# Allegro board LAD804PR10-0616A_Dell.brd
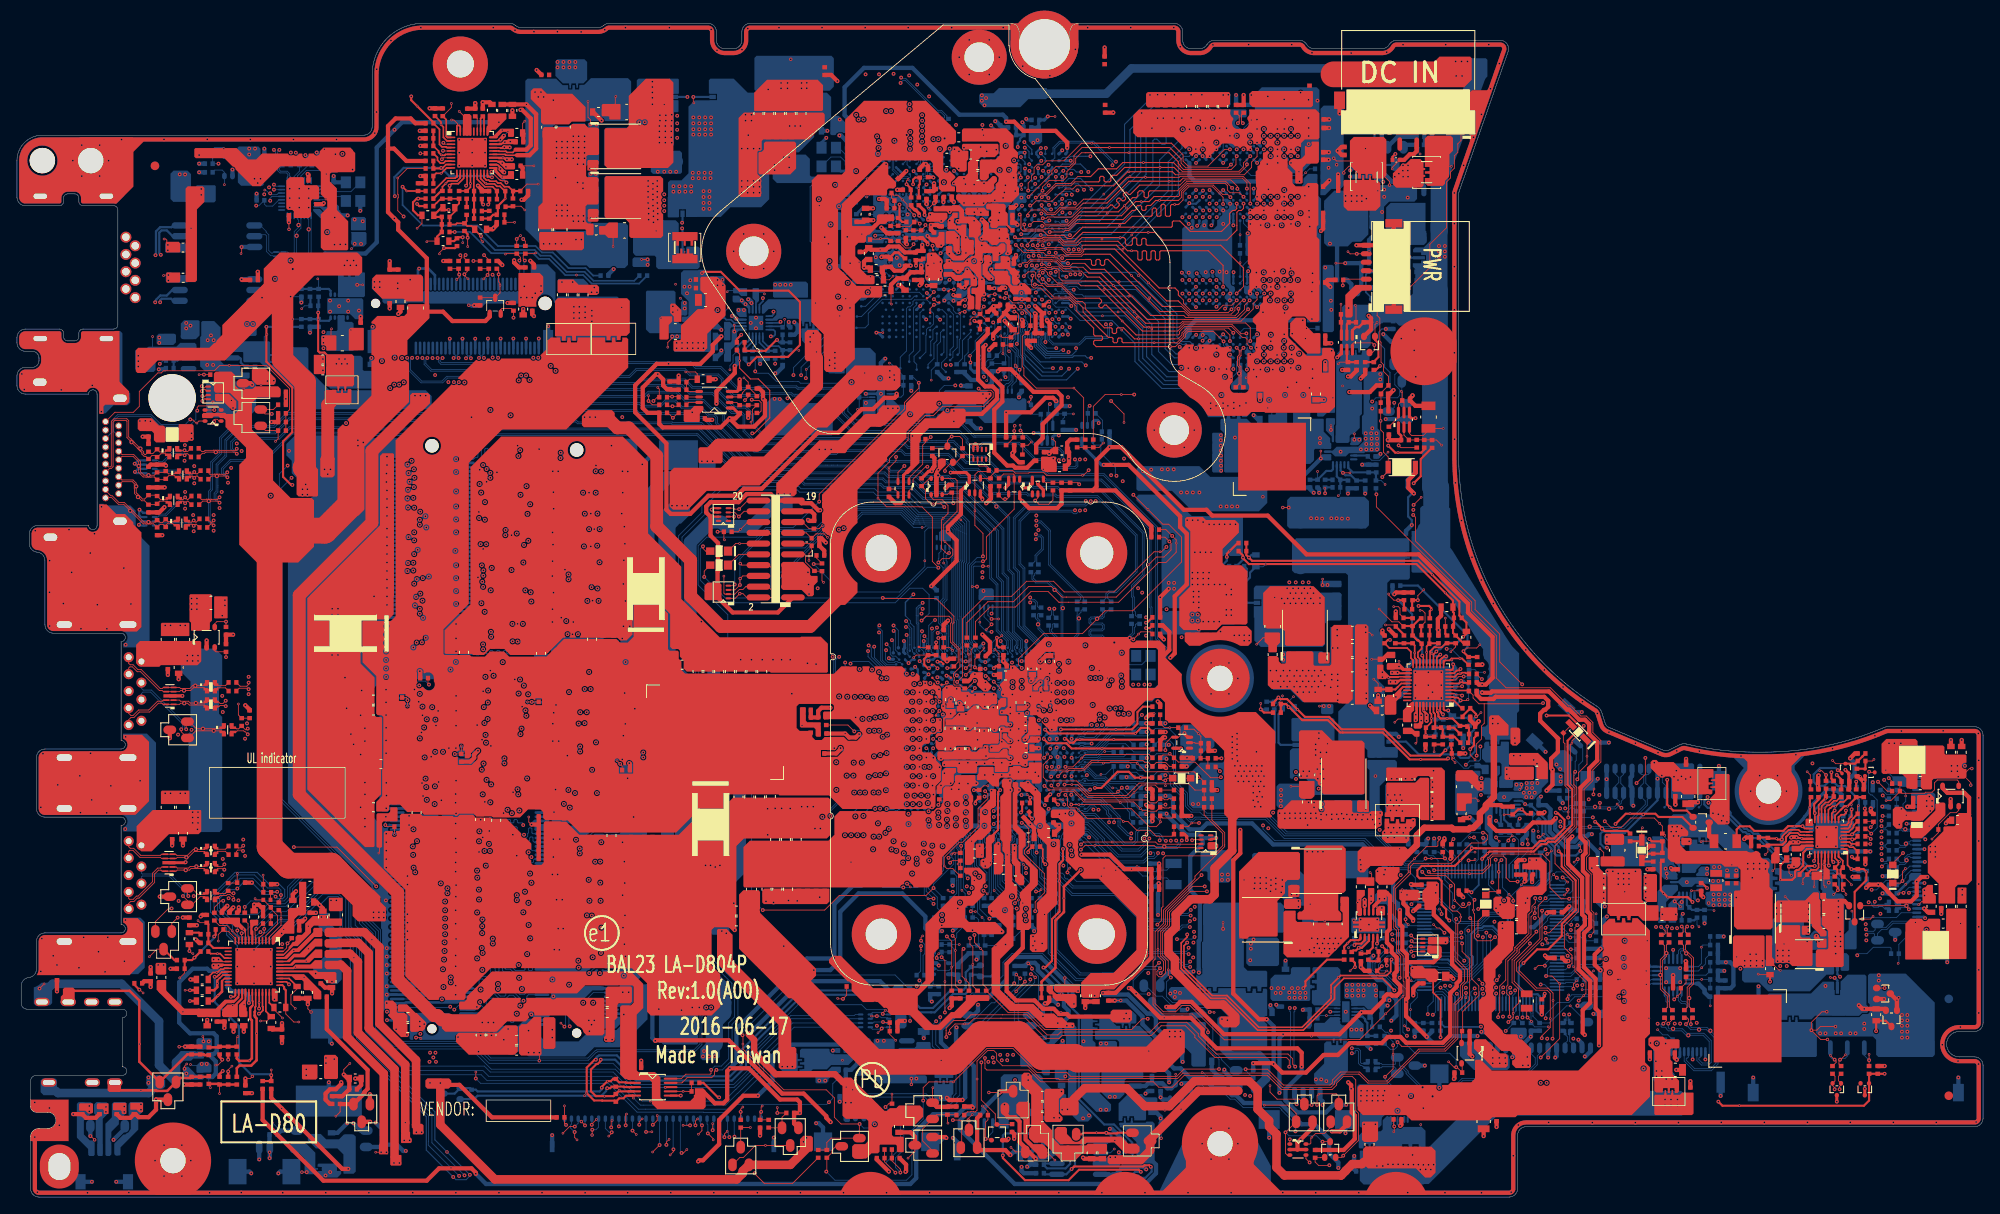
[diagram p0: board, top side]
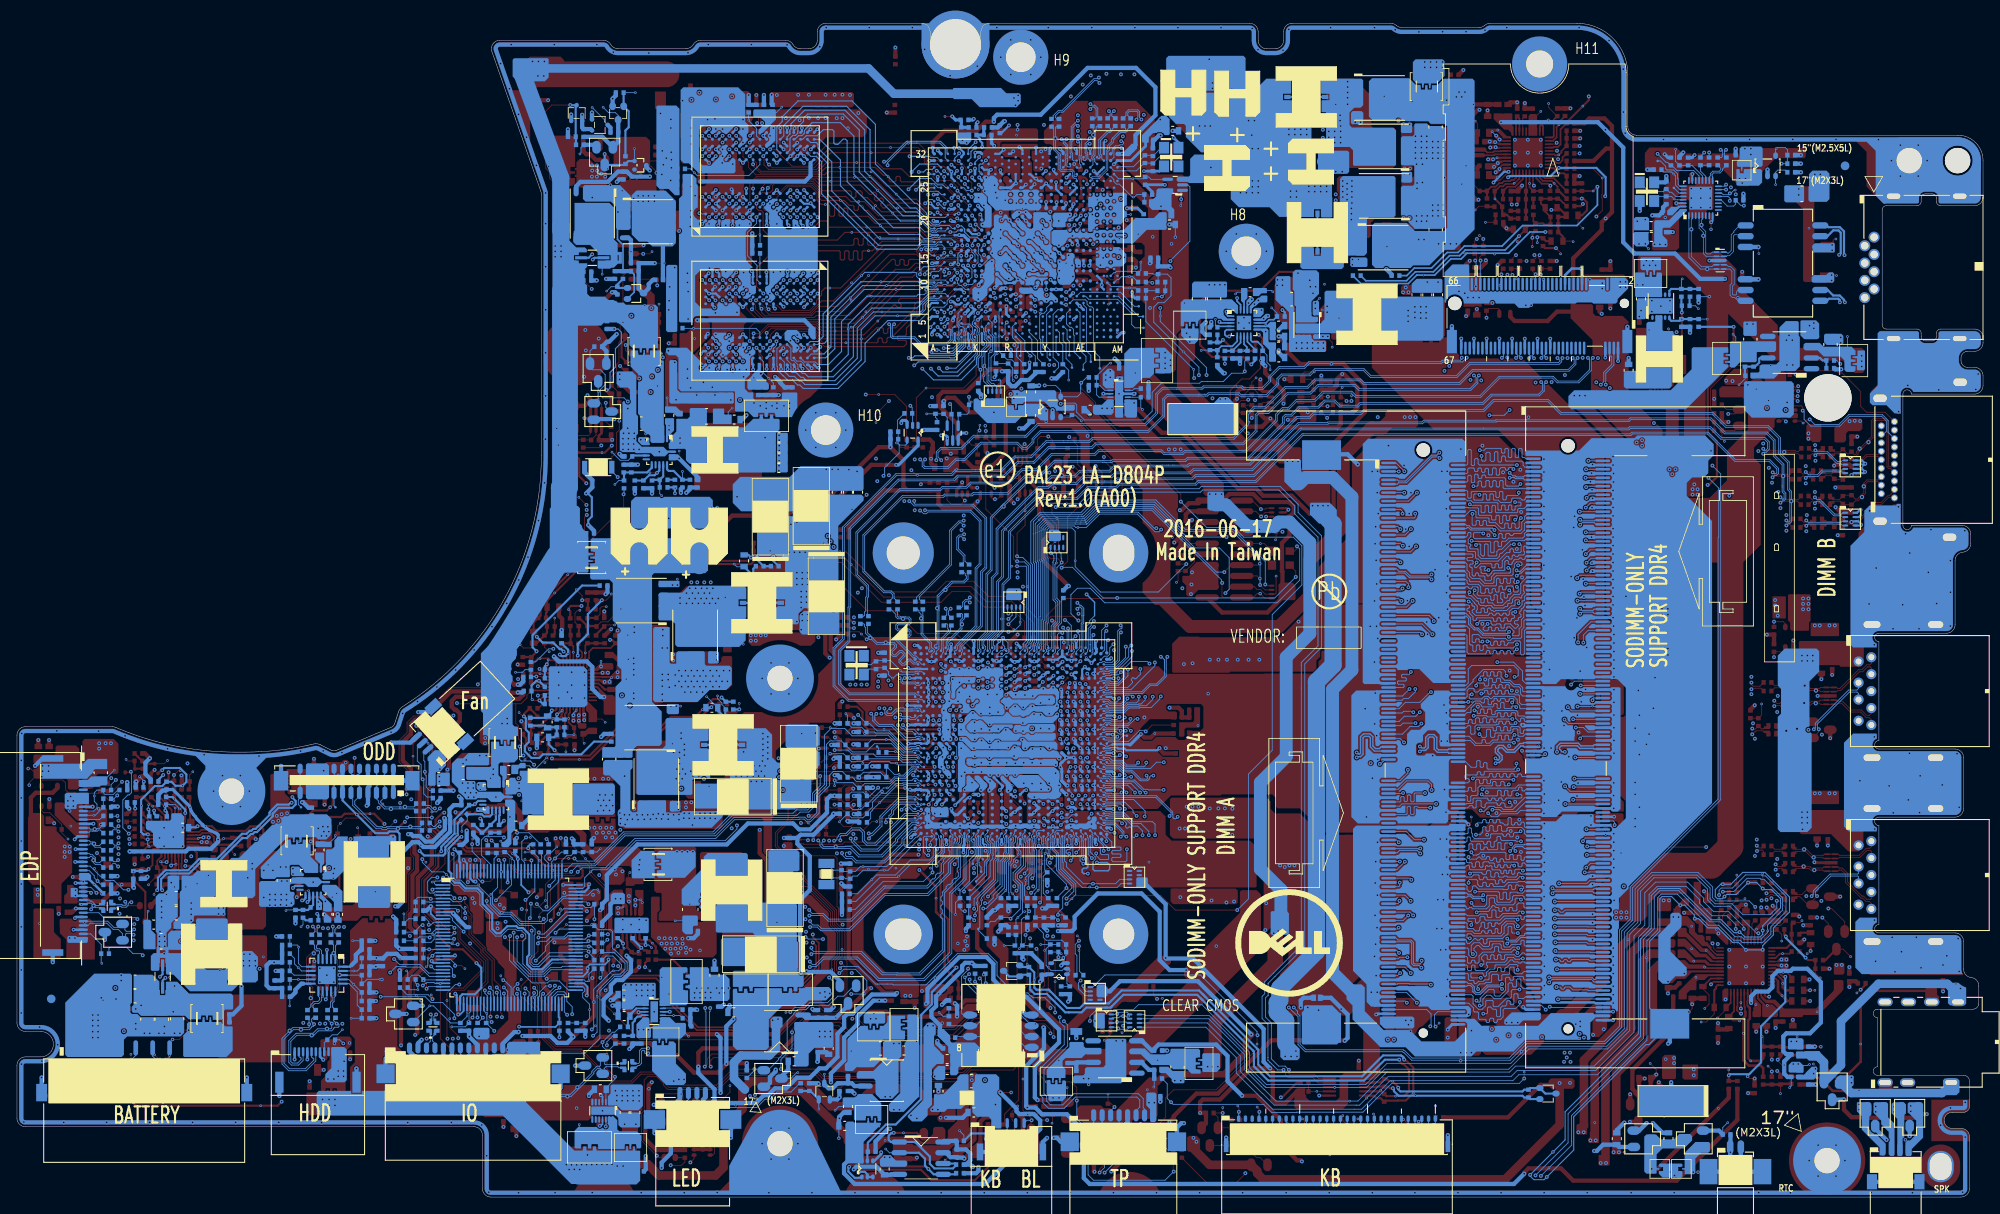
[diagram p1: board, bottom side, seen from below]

Outline 231.9 x 138.5 mm; copper layers: TOP, VCC, IN1, IN2, GND, BOTTOM. Coordinates in mm from the lower left corner of the outline.
Outline path: 0,122.3 arc(0.88,124.42) 3,125.3 40.9,125.3 arc(41.61,125.59) 41.9,126.3 41.9,132.5 arc(43.66,136.74) 47.9,138.5 58.13,138.5 arc(58.49,138.44) 58.8,138.25 arc(59.1,138.06) 59.46,138 68.54,138 arc(68.9,138.06) 69.2,138.25 arc(69.51,138.44) 69.87,138.5 81.5,138.5 arc(82.21,138.21) 82.5,137.5 82.5,136.5 arc(82.79,135.79) 83.5,135.5 84.5,135.5 arc(85.21,135.79) 85.5,136.5 85.5,137.5 arc(85.79,138.21) 86.5,138.5 117.2,138.5 arc(117.91,138.21) 118.2,137.5 118.2,136 arc(121.2,133) 124.2,136 124.2,137.5 arc(124.49,138.21) 125.2,138.5 136.5,138.5 arc(137.21,138.21) 137.5,137.5 137.5,136.5 arc(137.79,135.79) 138.5,135.5 139.5,135.5 arc(140,135.63) 140.37,136 arc(140.73,136.37) 141.23,136.5 151.27,136.5 arc(151.77,136.37) 152.13,136 arc(152.5,135.63) 153,135.5 161,135.5 arc(161.5,135.63) 161.87,136 arc(162.23,136.37) 162.73,136.5 174.94,136.5 arc(175.76,136.08) 175.88,135.17 170.11,118.66 arc(170.06,118.5) 170.05,118.33 170.05,87.5 arc(174.41,70.58) 186.41,57.88 arc(186.71,57.6) 186.91,57.23 187.34,55.9 arc(187.51,55.61) 187.79,55.41 194.19,52.72 arc(194.52,52.66) 194.85,52.74 196.1,53.36 arc(196.5,53.48) 196.92,53.46 arc(200.96,52.74) 205.05,52.5 206.05,52.5 arc(213.3,53.24) 220.25,55.42 arc(220.44,55.48) 220.64,55.5 230.9,55.5 arc(231.61,55.21) 231.9,54.5 231.9,20.54 arc(231.61,19.83) 230.9,19.54 229.1,19.54 arc(227.6,18.04) 229.1,16.54 230.9,16.54 arc(231.61,16.25) 231.9,15.54 231.9,9.3 arc(231.61,8.59) 230.9,8.3 178,8.3 arc(177.29,8.01) 177,7.3 177,1 arc(176.71,0.29) 176,0 2.6,0 arc(1.89,0.29) 1.6,1 1.6,7.1 arc(1.89,7.81) 2.6,8.1 3.65,8.1 arc(4.6,9.05) 3.65,10 2.3,10 arc(1.8,10.21) 1.6,10.7 1.6,13.67 arc(1.8,14.16) 2.3,14.37 12.45,14.37 arc(12.95,14.87) 12.45,15.37 12.45,21.17 arc(12.95,21.67) 12.45,22.17 1.2,22.17 arc(0.71,22.37) 0.5,22.87 0.5,24.91 arc(0.76,25.58) 1.4,25.91 arc(2.04,26.23) 2.3,26.9 2.3,30.17 arc(2.59,30.87) 3.3,31.17 12.28,31.17 arc(12.78,31.67) 12.28,32.17 12.28,43.83 arc(12.78,44.33) 12.28,44.83 3.3,44.83 arc(2.59,45.13) 2.3,45.83 2.3,51.87 arc(2.59,52.57) 3.3,52.87 12.28,52.87 arc(12.78,53.37) 12.28,53.87 12.28,65.53 arc(12.78,66.03) 12.28,66.53 4.3,66.53 arc(3.59,66.83) 3.3,67.53 3.3,75.1 arc(3.03,75.78) 2.38,76.1 arc(1.73,76.42) 1.46,77.09 1.46,78.25 arc(1.75,78.96) 2.46,79.25 8.45,79.25 arc(8.95,78.75) 9.45,79.25 9.45,94.75 arc(8.95,95.25) 8.45,94.75 1,94.75 arc(0.29,95.04) 0,95.75 0,96.9 arc(0.29,97.61) 1,97.9 1.8,97.9 arc(2.37,98.13) 2.6,98.7 2.6,99 arc(2.37,99.57) 1.8,99.8 1,99.8 arc(0.29,100.09) 0,100.8 0,101.42 arc(0.29,102.13) 1,102.42 5,102.42 arc(5.35,102.28) 5.5,101.92 5.5,101.52 arc(5.65,101.17) 6,101.02 6.8,101.02 arc(7.15,101.17) 7.3,101.52 7.3,101.92 arc(7.45,102.28) 7.8,102.42 11.4,102.42 arc(11.75,102.57) 11.9,102.92 11.9,116.48 arc(11.75,116.83) 11.4,116.98 7.8,116.98 arc(7.45,117.12) 7.3,117.48 7.3,117.88 arc(7.15,118.23) 6.8,118.38 6,118.38 arc(5.65,118.23) 5.5,117.88 5.5,117.48 arc(5.35,117.12) 5,116.98 1,116.98 arc(0.29,117.27) 0,117.98 0,122.3

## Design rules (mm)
net group CLK: nets 48M_X1 48M_X2
net group CLK_PCIE_LAN: nets CLK_PCIE_LAN CLK_PCIE_LAN#
net group CLK_PCIE_WLAN: nets CLK_PCIE_WLAN CLK_PCIE_WLAN#
net group CLK_PEG_VGA: nets CLK_PEG_VGA CLK_PEG_VGA#
net group DDRA_CLK0: nets DDRA_CLK0 DDRA_CLK0#
net group DDRA_CLK1: nets DDRA_CLK1 DDRA_CLK1#
net group DDRAB_SDQS0: nets DDRAB_SDQS0 DDRAB_SDQS0#
net group DDRAB_SDQS1: nets DDRAB_SDQS1 DDRAB_SDQS1#
net group DDRAB_SDQS2: nets DDRAB_SDQS2 DDRAB_SDQS2#
net group DDRAB_SDQS3: nets DDRAB_SDQS3 DDRAB_SDQS3#
net group DDRAB_SDQS4: nets DDRAB_SDQS4 DDRAB_SDQS4#
net group DDRAB_SDQS5: nets DDRAB_SDQS5 DDRAB_SDQS5#
net group DDRAB_SDQS6: nets DDRAB_SDQS6 DDRAB_SDQS6#
net group DDRAB_SDQS7: nets DDRAB_SDQS7 DDRAB_SDQS7#
net group DDRB_CLK0: nets DDRB_CLK0 DDRB_CLK0#
net group DDRB_CLK1: nets DDRB_CLK1 DDRB_CLK1#
net group DIFFPAIR2: nets A_MIC_CLK A_MIC_DATA
net group DIFFPAIR5: nets EC_SMB_CK1_R EC_SMB_DA1_R
net group DIFFPAIR6: nets EC_SMB_CK2 EC_SMB_DA2
net group DIFFPAIR7: nets EC_SMB_CK2_R EC_SMB_DA2_R
net group DIFFPAIR8: nets MIC_CLK_C MIC_DATA_C
net group DIFFPAIR9: nets TP_CLK TP_DATA
net group DIFFPAIR10: nets VGA_SMB_CK3 VGA_SMB_DA3
net group DIFFPAIR14: nets USB20_JUSB1_N2_R USB20_JUSB1_P2_R
net group DIFFPAIR15: nets SATA_RX_N0 SATA_RX_P0
net group EDP_TX0: nets EDP_TXN0 EDP_TXP0
net group EDP_TX0_C: nets EDP_TXN0_C EDP_TXP0_C
net group EDP_TX1: nets EDP_TXN1 EDP_TXP1
net group EDP_TX1_C: nets EDP_TXN1_C EDP_TXP1_C
net group GPCCLK_13/16_19/24: nets XTALIN XTALOUT
net group HDMI_DP1_TX0: nets HDMI_DP1_TXN0 HDMI_DP1_TXP0
net group HDMI_DP1_TX1: nets HDMI_DP1_TXN1 HDMI_DP1_TXP1
net group HDMI_DP1_TX2: nets HDMI_DP1_TXN2 HDMI_DP1_TXP2
net group HDMI_DP1_TX3: nets HDMI_DP1_TXN3 HDMI_DP1_TXP3
net group M_WCKA0_0: nets M_WCKA0_0 M_WCKA0_0#
net group M_WCKA0_1: nets M_WCKA0_1 M_WCKA0_1#
net group MDI0: nets MDI0+ MDI0-
net group MDI1: nets MDI1+ MDI1-
net group MDO0: nets MDO0+ MDO0-
net group MDO1: nets MDO1+ MDO1-
net group PCIE_ARX_DTX_0: nets PCIE_ARX_DTX_N0 PCIE_ARX_DTX_P0
net group PCIE_ARX_DTX_0_C: nets PCIE_ARX_DTX_N0_C PCIE_ARX_DTX_P0_C
net group PCIE_ARX_DTX_1: nets PCIE_ARX_DTX_N1 PCIE_ARX_DTX_P1
net group PCIE_ATX_C_DRX_0: nets PCIE_ATX_C_DRX_N0 PCIE_ATX_C_DRX_P0
net group PCIE_ATX_C_DRX_1: nets PCIE_ATX_C_DRX_N1 PCIE_ATX_C_DRX_P1
net group PCIE_ATX_DRX_0: nets PCIE_ATX_DRX_N0 PCIE_ATX_DRX_P0
net group PCIE_ATX_DRX_1: nets PCIE_ATX_DRX_N1 PCIE_ATX_DRX_P1
net group PEG_GTX_C_HRX_0: nets PEG_GTX_C_HRX_N0 PEG_GTX_C_HRX_P0
net group PEG_GTX_C_HRX_1: nets PEG_GTX_C_HRX_N1 PEG_GTX_C_HRX_P1
net group PEG_GTX_C_HRX_2: nets PEG_GTX_C_HRX_N2 PEG_GTX_C_HRX_P2
net group PEG_GTX_C_HRX_3: nets PEG_GTX_C_HRX_N3 PEG_GTX_C_HRX_P3
net group PEG_GTX_HRX_0: nets PEG_GTX_HRX_N0 PEG_GTX_HRX_P0
net group PEG_GTX_HRX_1: nets PEG_GTX_HRX_N1 PEG_GTX_HRX_P1
net group PEG_GTX_HRX_2: nets PEG_GTX_HRX_N2 PEG_GTX_HRX_P2
net group PEG_GTX_HRX_3: nets PEG_GTX_HRX_N3 PEG_GTX_HRX_P3
net group PEG_HTX_C_GRX_0: nets PEG_HTX_C_GRX_N0 PEG_HTX_C_GRX_P0
net group PEG_HTX_C_GRX_1: nets PEG_HTX_C_GRX_N1 PEG_HTX_C_GRX_P1
net group PEG_HTX_C_GRX_2: nets PEG_HTX_C_GRX_N2 PEG_HTX_C_GRX_P2
net group PEG_HTX_C_GRX_3: nets PEG_HTX_C_GRX_N3 PEG_HTX_C_GRX_P3
net group PEG_HTX_GRX_0: nets PEG_HTX_GRX_N0 PEG_HTX_GRX_P0
net group PEG_HTX_GRX_1: nets PEG_HTX_GRX_N1 PEG_HTX_GRX_P1
net group PEG_HTX_GRX_2: nets PEG_HTX_GRX_N2 PEG_HTX_GRX_P2
net group PEG_HTX_GRX_3: nets PEG_HTX_GRX_N3 PEG_HTX_GRX_P3
net group REMOTE1: nets REMOTE1+ REMOTE1-
net group REMOTE2: nets REMOTE2+ REMOTE2-
net group SATA_ARX_C_DTX_0: nets SATA_ARX_C_DTX_N0 SATA_ARX_C_DTX_P0
net group SATA_ARX_DTX_1: nets SATA_ARX_DTX_N1 SATA_ARX_DTX_P1
net group SATA_ARX_DTX_1_C: nets SATA_ARX_DTX_N1_C SATA_ARX_DTX_P1_C
net group SATA_ARX_RC_DTX_0: nets SATA_ARX_RC_DTX_N0 SATA_ARX_RC_DTX_P0
net group SATA_ARX_RC_DTX_0_C: nets SATA_ARX_RC_DTX_N0_C SATA_ARX_RC_DTX_P0_C
net group SATA_ATX_C_DRX_0: nets SATA_ATX_C_DRX_N0 SATA_ATX_C_DRX_P0
net group SATA_ATX_DRX_1: nets SATA_ATX_DRX_N1 SATA_ATX_DRX_P1
net group SATA_ATX_DRX_1_C: nets SATA_ATX_DRX_N1_C SATA_ATX_DRX_P1_C
net group SATA_ATX_RC_DRX_0: nets SATA_ATX_RC_DRX_N0 SATA_ATX_RC_DRX_P0
net group SATA_ATX_RC_DRX_0_C: nets SATA_ATX_RC_DRX_N0_C SATA_ATX_RC_DRX_P0_C
net group TMDS_L_TX0: nets TMDS_L_TX0N TMDS_L_TX0P
net group TMDS_L_TX1: nets TMDS_L_TX1N TMDS_L_TX1P
net group TMDS_L_TX2: nets TMDS_L_TX2N TMDS_L_TX2P
net group TMDS_L_TXC: nets TMDS_L_TXCN TMDS_L_TXCP
net group TMDS_TX0: nets TMDS_TX0N TMDS_TX0P
net group TMDS_TX1: nets TMDS_TX1N TMDS_TX1P
net group TMDS_TX2: nets TMDS_TX2N TMDS_TX2P
net group TMDS_TXC: nets TMDS_TXCN TMDS_TXCP
net group USB3R1_JUSB1: nets USB3RN1_JUSB1 USB3RP1_JUSB1
net group USB3R1_JUSB1_R: nets USB3RN1_JUSB1_R USB3RP1_JUSB1_R
net group USB3R2_JUSB2: nets USB3RN2_JUSB2 USB3RP2_JUSB2
net group USB3R2_JUSB2_R: nets USB3RN2_JUSB2_R USB3RP2_JUSB2_R
net group USB3T1_JUSB1: nets USB3TN1_JUSB1 USB3TP1_JUSB1
net group USB3T1_JUSB1_C: nets USB3TN1_JUSB1_C USB3TP1_JUSB1_C
net group USB3T1_JUSB1_R: nets USB3TN1_JUSB1_R USB3TP1_JUSB1_R
net group USB3T2_JUSB2: nets USB3TN2_JUSB2 USB3TP2_JUSB2
net group USB3T2_JUSB2_C: nets USB3TN2_JUSB2_C USB3TP2_JUSB2_C
net group USB3T2_JUSB2_R: nets USB3TN2_JUSB2_R USB3TP2_JUSB2_R
net group USB20: nets USB20_JUSB1_N2 USB20_JUSB1_P2
net group USB20_CAM_3: nets USB20_CAM_N3 USB20_CAM_P3
net group USB20_CAM_3_R: nets USB20_CAM_N3_R USB20_CAM_P3_R
net group USB20_CR_0: nets USB20_CR_N0 USB20_CR_P0
net group USB20_CR_0_R: nets USB20_CR_N0_R USB20_CR_P0_R
net group USB20_JUSB1_5: nets USB20_JUSB1_N5 USB20_JUSB1_P5
net group USB20_JUSB1_5_R: nets USB20_JUSB1_N5_R USB20_JUSB1_P5_R
net group USB20_JUSB2_6: nets USB20_JUSB2_N6 USB20_JUSB2_P6
net group USB20_JUSB2_6_R: nets USB20_JUSB2_N6_R USB20_JUSB2_P6_R
net group USB20_MINI1_4: nets USB20_MINI1_N4 USB20_MINI1_P4
net group USB20_TOUCH_1: nets USB20_TOUCH_N1 USB20_TOUCH_P1
net group VRAM_DBI_19/20_25: nets M_DBI0# M_DBI3#
net group VRAM_EDC_26/28_25: nets M_EDC_0 M_EDC_3
net group 8/12: nets HDA_SDIN0 HDA_SDIN0_R HDA_SDIN1 HDA_SDIN2
net group 10: nets +FB1_VREFCL +FB1_VREFDL +LINE1-VREFO-L +LINE1-VREFO-R +MVREFDA +MVREFSA APU_VDDIO_MEM_S3_FB_H APU_VDDP_RUN_FB_H APU_VDDP_RUN_FB_L AUD_HP1_JACK_L1 AUD_HP1_JACK_R1 HPOUT-L HPOUT-R LINE1-L LINE1-L_C LINE1-L_R LINE1-R
net group 15: nets +MEM_VREF LPC_CLK0_EC LPC_CLK1
net group AUDIO-PHONE: nets RING2 RING2_R SLEEVE SLEEVE_R
net group AUDIO-SPK: nets INT-SPK-L+ INT-SPK-L- INT-SPK-R+ INT-SPK-R- SPK_L+_CONN SPK_L-_CONN SPK_R+_CONN SPK_R-_CONN
net group AUX-DISPLAY: nets APU_HDMI_CLK APU_HDMI_DATA CPU_DPB_CTRLCLK_R CPU_DPB_CTRLDAT_R EDP_AUXN EDP_AUXN_C EDP_AUXP EDP_AUXP_C
net group DDR: nets DDRAB_SDM0 DDRAB_SDM1 DDRAB_SDM2 DDRAB_SDM3 DDRAB_SDM4 DDRAB_SDM5 DDRAB_SDM6 DDRAB_SDM7 DDRAB_SDQ0 DDRAB_SDQ1 DDRAB_SDQ2 DDRAB_SDQ3 DDRAB_SDQ4 DDRAB_SDQ5 DDRAB_SDQ6 DDRAB_SDQ7 DDRAB_SDQ8 DDRAB_SDQ9 DDRAB_SDQ10 DDRAB_SDQ11 DDRAB_SDQ12 DDRAB_SDQ13 DDRAB_SDQ14 DDRAB_SDQ15 DDRAB_SDQ16 DDRAB_SDQ17 DDRAB_SDQ18 DDRAB_SDQ19 DDRAB_SDQ20 DDRAB_SDQ21 DDRAB_SDQ22 DDRAB_SDQ23 DDRAB_SDQ24 DDRAB_SDQ25 DDRAB_SDQ26 DDRAB_SDQ27 DDRAB_SDQ28 DDRAB_SDQ29 DDRAB_SDQ30 DDRAB_SDQ31 DDRAB_SDQ32 DDRAB_SDQ33 DDRAB_SDQ34 DDRAB_SDQ35 DDRAB_SDQ36 DDRAB_SDQ37 DDRAB_SDQ38 DDRAB_SDQ39 DDRAB_SDQ40 DDRAB_SDQ41 DDRAB_SDQ42 DDRAB_SDQ43 DDRAB_SDQ44 DDRAB_SDQ45 DDRAB_SDQ46 DDRAB_SDQ47 DDRAB_SDQ48 DDRAB_SDQ49 DDRAB_SDQ50 DDRAB_SDQ51 DDRAB_SDQ52 DDRAB_SDQ53 DDRAB_SDQ54 DDRAB_SDQ55 DDRAB_SDQ56 DDRAB_SDQ57 DDRAB_SDQ58 DDRAB_SDQ59 DDRAB_SDQ60 DDRAB_SDQ61 DDRAB_SDQ62 DDRAB_SDQ63
net group DDRADD_12_25: nets DDRAB_BG0 DDRAB_BG1 DDRAB_SBS0# DDRAB_SBS1# DDRAB_SCAS# DDRAB_SMA0 DDRAB_SMA1 DDRAB_SMA2 DDRAB_SMA3 DDRAB_SMA4 DDRAB_SMA5 DDRAB_SMA6 DDRAB_SMA7 DDRAB_SMA8 DDRAB_SMA9 DDRAB_SMA10 DDRAB_SMA11 DDRAB_SMA12 DDRAB_SMA13 DDRAB_SRAS# DDRAB_SWE# MEM_MAB_ACT#
net group DDRCTL_12_25: nets DDRA_CKE0 DDRA_CKE1 DDRA_ODT0 DDRA_ODT1 DDRA_SCS0# DDRA_SCS1# DDRB_CKE0 DDRB_CKE1 DDRB_ODT0 DDRB_ODT1 DDRB_SCS0# DDRB_SCS1#
net group HDA: nets HDA_BITCLK HDA_BITCLK_AUDIO HDA_RST HDA_RST#_AUDIO HDA_SDOUT HDA_SDOUT_AUDIO HDA_SYNC HDA_SYNC_AUDIO
net group I2C: nets APU_I2C1_SCL APU_I2C1_SDA I2C_CLK_TP I2C_DAT_TP
net group KB: nets KSI0 KSI1 KSI2 KSI3 KSI4 KSI5 KSI6 KSI7 KSO0 KSO1 KSO2 KSO3 KSO4 KSO5 KSO6 KSO7 KSO8 KSO9 KSO10 KSO11 KSO12 KSO13 KSO14 KSO15 KSO16
net group LPC: nets LPC_AD0 LPC_AD1 LPC_AD2 LPC_AD3 LPC_FRAME# LPC_RST_A# SERIRQ
net group RTC-CLK: nets 32K_X1 32K_X2 RTC_CLK
net group SATA: nets SATA_ARX_DTX_N0 SATA_ARX_DTX_P0 SATA_ATX_DRX_N0 SATA_ATX_DRX_P0 SATA_TX_N0 SATA_TX_P0
net group SMBUS: nets CLK_SMB DAT_SMB EC_SMB_CK1 EC_SMB_DA1
net group SPI: nets APU_SPI_CLK APU_SPI_CLK_R APU_SPI_CS1# APU_SPI_CS1#_R APU_SPI_HOLD# APU_SPI_MISO APU_SPI_MOSI APU_SPI_TPMCS# APU_SPI_WP#
net group SVID: nets APU_SVC APU_SVC_R APU_SVD APU_SVD_R APU_SVT APU_SVT_R N16808781 N16808782 N16808783 SVI2_SVC SVI2_SVD SVI2_SVT
net group VRAM_ADBI_19/20_25: nets M_ADBI0
net group VRAM_CTL_12_25: nets M_CKE0
net group VRAM_DA_13/12_25: nets M_DA24 M_DA25 M_DA26 M_DA27 M_DA28
nets with their own width: min track width 0.102; nets BATT_CHG_LED BATT_CHG_LED# BATT_CHG_LED_R# BATT_LOW_LED BATT_LOW_LED# BATT_LOW_LED_R# PWR_LED# PWR_LED_R# WHITE_LED_PWR
nets with their own width: min track width 0.203; nets N20135126 N20135171 VSUM-_VGA
nets with their own width: min track width 0.254; nets 0.95_1.8VALW_PWREN 5V_FB +0.95VALWP +0.775MOS +1.8VALWP +1.35V_MEM_GFX +1.35VGPUP +17.4V_BATT+ +19VB_1.2V ACIN_CHG ACLIM APU_VDD_RUN_FB_L APU_VDD_SEN ASGATE AUD_SENSE_A BATT_TEMP CCLIM CMSRC COMP CORE_NB_GATE EN_0.6VSP EN_1.2V EN_1.8VALW EN_2.5V EN_3V EN_5V EN_+1.35VGPU EN_VDDP_ALWP ENABLE_APU ENABLE_VGA ENLDO_3V5V FB_1.2V FB_1.8VALW FB_+1.35VGPU FB_VDDP_ALWP ILMT_+1.35VGPU IMON_APU IMON_NB IMON_VGA ISEN1_VGA ISEN2_VGA JACK_PLUG_DET JACK_SENSE# JACK_SENSE_1# MIC1-L N17735595 N20135010 N20135022 N20135039 N20135040 N20135043 N20135096 N20135098 N20135134 N20135137 N20135141 N20135184 N20135219 N20135258 N20135264 N20141258 N20141272 N20141325 N20141337 N20141361 N20141372 N20141380 N20141402 N20141406 N20141448 N20141457 N20141459 N20141467 N20141469 N20141501 N20141511 N20141517 N20141713 N20141862 N20141864 N20141906 N20141912 N20141916 N20141920 N20141926 N20142021 N20142108 N20142189 N20277811 N20277821 N21204075 N21204078 N21204129 N21230662 N22661869 N22664360 N22664751 N22664968 N22666744 N23674571 N24135897 N24135899 N24924773 N27920326 N28484391 N28484395 N28484412 N28484439 N28714524 N28714554 N28714559 N28714562 N28714572 N28714582 N28714583 N28714585 N28714598 N28714599 N28714601 N28714604 N28714608 N28714612 N28714614 N28714625 N28714721 N28714724 N28714752 N28714753 N29189918 N33726059 N33745668 N39282188 N39352755 OCP_L POK PROG PROH RF_VDDP_ALWP TON_1.2V TRIP_VDDP_ALWP V3D3_STB VCCSENSE_VGA VCOUT0_PH# VDD_CHG VDDIO_APU VDDIO_VGA VDDP_CHG VGATE VSSSENSE_VGA VSUM+_APU VSUM+_VGA VSUM-_APU VSUMN_NB VSUMP_NB VTTREF_1.2V
nets with their own width: min track width 0.305; nets +3VS_APU AUD_PORTA_L_R_B AUD_PORTA_R_R_B IR_GND VDDIO_AUDIO
nets with their own width: min track width 0.381; nets APU_MAB_VREFDQ
nets with their own width: min track width 0.508; nets 0.95VS_GATE 0.775VALW_GATE 5VS +0.95VS +0.95VS_APU_GFX +0.95VSDGPU +0.775VALW +1.2VP +1.5VS +1.8V_AVDD +1.8VGS +1.8VS +3V_1.8V_CPVDD +3VALW +3VALW_EC +3VALWP +3VGS +3VLP +3VS +5V_PVDD +5VALW +5VALWP +5VS +19V_VIN +APU_CORE +APU_CORE_NB +CHGRTC +EC_VCCA +LAN_VDD10 +MIC2-VREFO +MPLL_PVDD +RTC_APU +RTC_APU_R +RTCBATT +RTCVCC +SPI_VCC +SPLL_PVDD +SPLL_VDDC +V18R +V_DAC +VDD_CT +VDDCR_FCH_ALW +VGA_CORE +VREF_CA ADJ_1.5VS BA EN_1.5VS GND GNDA LX_3V LX_+1.35VGPU N17382836 N20135024 N21024549 N22673637 N23435447 N23700319 N24106209 N24106231 N27286345 N27700813 N27705118 PSID VL VSS_MECH
nets with their own width: min track width 0.635; nets +3V_DVDD
nets with their own width: min track width 0.762; nets +3VS_CAM +3VS_TOUCH +5V_AVDD +5VS_KBL +VDD_TOUCH BST1_APU BST_NB BST_VDDP_ALWP ECAGND LG1_APU LG1_VGA LG2_VGA LG_1.2V LG_NB LG_VDDP_ALWP LGATE_CHG LX1_APU LX1_VGA LX2_VGA LX_1.2V LX_NB LX_VDDP_ALWP N20277901 N21021316 N21022260 N21022300 N28714606 PHASE_CHG UG1_APU UG1_VGA UG2_VGA UG_1.2V UG_NB UG_VDDP_ALWP
nets with their own width: min track width 1.016; nets 1.5VS_VIN +1.5VSP +1.8V_ALW T-GND_L
nets with their own width: min track width 1.219; nets +0.95VALW
nets with their own width: min track width 1.524; nets +0.6V_DDR_VTT +2.5V_MEM +5V_HDMI +LAN_VDD33 +LAN_VDDREG
nets with their own width: min track width 2.032; nets +19VB +DCBAT_CAM +INV_PWR_SRC
nets with their own width: min track width 2.286; nets +5VS_ODD +LCDVDD +LCDVDD_CONN
nets with their own width: min track width 3.048; nets +3VS_WLAN_NGFF +5V_HDD +5V_USB_PWR1 +5V_USB_PWR2 +BIF_VDDC
nets with their own width: min track width 3.81; nets +1.2V_DDR

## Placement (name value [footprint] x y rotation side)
C2  0.1U_0402_16V7K  [C_0402]  224.57 46.06 180 top
C3  1U_0402_10V6K  [C_0402]  224.57 47.07 180 top
C4  10U_0603_25V6M  [C_0603]  228.11 51.77 90 top
C5  0.1U_0603_25V7K  [C_0603]  229.38 51.77 90 top
C6  0.1U_0402_16V7K  [C_0402]  56.6 109.54 90 top
C16  .1U_0402_16V7K  [C_0402]  137.43 21.15 90 bottom
C17  4.7U_0603_6.3V6K  [C_0603]  229.6 44.47 180 top
C18  4.7U_0603_6.3V6K  [C_0603]  225.83 35.01 270 top
C19  1U_0402_6.3V6K~D  [C_0402]  97.95 11.89 180 bottom
C22  .1U_0402_16V7K  [C_0402]  109.75 10.64 270 top
C24  1U_0402_6.3V6K  [C_0402]  158.26 18.1 90 bottom
C26  .1U_0402_16V7K  [C_0402]  152.36 20.16 0 bottom
C27  10P_0402_50V8J  [C_0402]  119.65 32.99 270 bottom
C34  10U_0603_10V6M  [C_0603]  118.32 9.99 0 bottom
C35  0.1U_0402_25V6K  [C_0402]  128.35 127.96 90 top
C36  0.1U_0402_25V6K  [C_0402]  164.17 108.16 0 bottom
C37  0.1U_0402_25V6K  [C_0402]  152.46 130.23 90 top
C38  0.1U_0402_25V6K  [C_0402]  162.33 102.43 90 bottom
C39  0.1U_0402_25V6K  [C_0402]  95.27 132.4 90 top
C40  0.1U_0402_25V6K  [C_0402]  128.29 134.59 270 top
C41  1000P_0402_50V7K  [C_0402]  62.77 132.42 180 top
C42  1000P_0402_50V7K  [C_0402]  196.62 42.89 270 top
C43  1000P_0402_50V7K  [C_0402]  164.75 78.31 180 bottom
C44  1000P_0402_50V7K  [C_0402]  175.58 54.88 0 top
C45  1000P_0402_50V7K  [C_0402]  197.12 45.03 90 bottom
C46  1U_0402_6.3V6K  [C_0402]  137.43 18 270 bottom
C47  1000P_0402_50V7K  [C_0402]  165.07 109.18 180 bottom
C48  1000P_0402_50V7K  [C_0402]  162.58 39.59 270 top
C49  1000P_0402_50V7K  [C_0402]  195.85 39.59 270 top
C343  2200P_0402_25V7K  [C_0402]  98.43 95.4 0 bottom
C344  2200P_0402_25V7K  [C_0402]  98.43 94.38 0 bottom
C349  330P_0402_50V7K  [C_0402]  152.47 21.1 0 bottom
C431  22U_0603_6.3V6M  [C_0603]  120.23 11.96 0 top
C432  22U_0603_6.3V6M  [C_0603]  120.23 9.42 0 top
C551  100P_0402_50V8J  [C_0402]  102.33 4.59 180 top
C553  100P_0402_50V8J  [C_0402]  103.19 4.59 0 top
C620  1U_0603_16V7  [C_0603]  112.29 95.71 270 bottom
C621  4.7U_0603_6.3V6K  [C_0603]  112.29 91.52 90 bottom
C622  .1U_0402_16V7K  [C_0402]  101.81 92.47 180 bottom
C623  4.7U_0603_6.3V6K  [C_0603]  106.03 92.91 180 bottom
C625  .1U_0402_16V7K  [C_0402]  101.9 97.8 180 bottom
C636  10P_0402_50V8J  [C_0402]  121.98 22.29 90 bottom
C796  5.6P_0402_50V8D  [C_0402]  129.56 62.45 270 bottom
C797  5.6P_0402_50V8D  [C_0402]  129.56 63.31 90 bottom
C939  4.7U_0603_6.3V6K  [C_0603]  136.16 18.24 270 bottom
C940  4.7U_0603_6.3V6K  [C_0603]  146.64 21.8 0 bottom
C983  0.22U_0402_10V6K  [C_0402]  105.47 95.79 180 bottom
C987  0.1U_0402_16V7K  [C_0402]  159.28 18.1 90 bottom
C2305  10U_0603_10V6M  [C_0603]  158.96 10.69 270 bottom
C2306  10U_0603_10V6M  [C_0603]  160.23 10.69 270 bottom
C2307  .1U_0402_16V7K  [C_0402]  158.87 3.04 180 bottom
C2308  10U_0603_10V6M  [C_0603]  159.53 5.48 90 top
C2309  0.01U_0603_25V7K  [C_0603]  162.39 12.72 0 bottom
C2316  10U_0603_6.3V6M  [C_0603]  159.6 22.62 0 bottom
C2318  10U_0603_6.3V6M  [C_0603]  159.6 23.89 0 bottom
C2322  0.01U_0603_25V7K  [C_0603]  160.99 21.35 180 bottom
C2323  10U_0603_10V6M  [C_0603]  149.63 25.48 90 bottom
C2324  .1U_0402_16V7K  [C_0402]  149.18 23.39 270 bottom
C2498  0.1U_0402_10V6K  [C_0402]  72.71 15.26 0 top
C2500  2200P_0402_25V7K  [C_0402]  53.61 12.67 270 bottom
C2502  2200P_0402_25V7K  [C_0402]  70.63 13.94 270 top
C2504  2200P_0402_25V7K  [C_0402]  70.63 12.16 270 top
C2505  2200P_0402_25V7K  [C_0402]  112.54 26.23 90 bottom
C2618  4.7U_0603_6.3V6K  [C_0603]  129.56 4.02 270 bottom
C2619  4.7U_0603_6.3V6K  [C_0603]  133.56 8.4 0 bottom
C2620  4.7U_0603_6.3V6K  [C_0603]  128.04 5.92 270 top
C2621  4.7U_0603_6.3V6K  [C_0603]  126.77 5.92 270 top
C2622  4.7U_0603_6.3V6K  [C_0603]  120.23 10.69 0 top
C4311  0.1U_0402_16V7K  [C_0402]  221.71 41.93 180 bottom
C4312  0.1U_0402_16V7K  [C_0402]  221.71 40.91 180 bottom
C4313  0.1U_0402_16V7K  [C_0402]  221.71 39.9 180 bottom
C4314  0.1U_0402_16V7K  [C_0402]  221.71 38.88 180 bottom
C4321  0.1U_0402_16V7K  [C_0402]  221.71 43.96 180 bottom
C4322  0.1U_0402_16V7K  [C_0402]  221.71 42.94 180 bottom
C5216  470P_0402_50V7K  [C_0402]  162.38 9.16 0 top
C5219  470P_0402_50V7K  [C_0402]  153.39 22.12 180 bottom
CA1  10U_0603_10V6M  [C_0603]  36.09 32.34 90 top
CA2  .1U_0402_16V7K  [C_0402]  33.29 30.55 90 top
CA3  10U_0603_10V6M  [C_0603]  37.1 26.12 270 top
CA4  .1U_0402_16V7K  [C_0402]  35.83 26.13 270 top
CA5  4.7U_0603_6.3V6K  [C_0603]  33.61 34.82 0 top
CA6  .1U_0402_16V7K  [C_0402]  33.6 33.55 0 top
CA8  10P_0402_50V8J  [C_0402]  29.06 36.91 0 top
CA10  .1U_0402_16V7K  [C_0402]  23.58 21.62 270 top
CA11  4.7U_0603_10V6K  [C_0603]  22.44 21.61 270 top
CA12  4.7U_0603_6.3V6K  [C_0603]  34.31 24.85 270 top
CA13  4.7U_0603_6.3V6K  [C_0603]  39.2 13.99 0 top
CA14  .1U_0402_16V7K  [C_0402]  39.19 12.72 0 top
CA15  4.7U_0603_6.3V6K  [C_0603]  32.53 33.61 90 top
CA16  .1U_0402_16V7K  [C_0402]  32.33 32.53 0 top
CA17  .1U_0402_16V7K  [C_0402]  25.98 32.64 90 top
CA20  4.7U_0603_6.3V6K  [C_0603]  25.55 20.21 90 top
CA21  10U_0603_6.3V6M  [C_0603]  33.04 23.45 90 top
CA22  4.7U_0603_6.3V6K  [C_0603]  27.97 33.76 270 top
CA23  2.2U_0603_6.3V6K  [C_0603]  26.75 21.61 270 top
CA24  1U_0603_16V7  [C_0603]  30.31 22.37 0 top
CA25  1U_0603_16V7  [C_0603]  29.99 19.89 90 top
CA26  10U_0603_6.3V6M  [C_0603]  22.56 25.67 180 top
CA27  1000P_0402_50V7K  [C_0402]  7.7 10.7 270 top
CA28  1000P_0402_50V7K  [C_0402]  9.74 10.7 270 top
CA29  1000P_0402_50V7K  [C_0402]  11.77 10.7 270 top
CA30  1000P_0402_50V7K  [C_0402]  13.8 10.7 270 top
CA31  22P_0402_50V8J  [C_0402]  29.94 33.17 180 top
CA32  10U_0603_10V6M  [C_0603]  22.56 23.13 180 top
CA33  10U_0603_10V6M  [C_0603]  22.56 24.4 180 top
CA34  100P_0402_50V8J  [C_0402]  20.59 16.83 90 top
CA35  100P_0402_50V8J  [C_0402]  20.59 14.19 270 top
CA36  100P_0402_50V8J  [C_0402]  20.59 14.19 270 bottom
CA37  100P_0402_50V8J  [C_0402]  20.59 16.83 90 bottom
CA39  6.8P_0402_50V  [C_0402]  29.94 34.18 180 top
CA40  .1U_0402_16V7K  [C_0402]  22.58 29.99 180 top
CA41  0.1U_0402_16V7K  [C_0402]  22.58 28.97 180 top
CA42  0.1U_0402_16V7K  [C_0402]  23.44 31.58 0 top
CC14  0.1U_0402_16V7K  [C_0402]  111.02 26.23 90 bottom
CC15  0.1U_0402_16V7K  [C_0402]  110.26 24.35 270 top
CC16  150P_0402_50V8J  [C_0402]  107.72 24.86 270 bottom
CC23  100P_0402_50V8J  [C_0402]  139.64 53.55 0 top
CC29  1000P_0402_50V7K  [C_0402]  92.72 56.6 0 top
CC30  22P_0402_50V8J  [C_0402]  113.3 29.69 270 bottom
CC31  0.1U_0402_16V7K  [C_0402]  137.38 42.82 180 top
CC32  0.1U_0402_16V7K  [C_0402]  132.56 46.31 180 bottom
CC50  0.1U_0402_16V7K  [C_0402]  111.78 60.01 90 top
CC51  0.1U_0402_16V7K  [C_0402]  110.51 62.62 90 top
CC52  0.1U_0402_16V7K  [C_0402]  132.56 48.28 180 bottom
CC53  0.1U_0402_16V7K  [C_0402]  129.36 49.55 0 bottom
CC99  0.1U_0402_16V7K  [C_0402]  93.63 57.49 180 top
CC119  0.1U_0603_25V7K  [C_0603]  43.2 6.18 90 bottom
CC120  680P_0603_50V8J  [C_0603]  37.1 6.18 90 bottom
CC166  0.22U_0402_10V6K  [C_0402]  133.8 37.67 0 top
CC203  1U_0402_6.3V6K  [C_0402]  93.24 41.72 90 top
CC224  .1U_0402_16V7K  [C_0402]  131.47 67.63 90 bottom
CC225  .1U_0402_16V7K  [C_0402]  132.42 67.63 90 bottom
CC226  .1U_0402_16V7K  [C_0402]  128.04 69.35 90 bottom
CC227  .1U_0402_16V7K  [C_0402]  129.05 69.35 90 bottom
CC245  180P_0402_50V8J  [C_0402]  112.59 49.48 0 top
CC615  150P_0402_50V8J  [C_0402]  110.76 32.99 270 bottom
CC635  .1U_0402_16V7K  [C_0402]  121.74 17.54 0 bottom
CC682  22P_0402_50V8J  [C_0402]  133.62 38.42 90 bottom
CC686  18P_0402_50V8J  [C_0402]  133.62 37.56 270 bottom
CC912  150P_0402_50V8J  [C_0402]  136.47 51.83 0 top
CC923  1U_0402_6.3V6K  [C_0402]  133.8 38.69 0 top
CC934  10U_0603_6.3V6M  [C_0603]  85.55 32.53 180 top
CC935  10U_0603_6.3V6M  [C_0603]  85.55 33.8 180 top
CC949  10U_0603_6.3V6M  [C_0603]  88.41 37.04 270 top
CC950  10U_0603_6.3V6M  [C_0603]  91.97 41.48 90 top
CC951  10U_0603_6.3V6M  [C_0603]  90.95 37.04 270 top
CC999  .1U_0402_16V7K  [C_0402]  138.69 51.77 0 top
CC1000  .1U_0402_16V7K  [C_0402]  140.56 52.66 180 top
CC1005  1U_0402_6.3V6K  [C_0402]  122.7 23.63 90 top
CC1006  1U_0402_6.3V6K  [C_0402]  123.59 23.63 90 top
CC1007  1U_0402_6.3V6K  [C_0402]  124.48 23.63 90 top
CC1008  22U_0603_6.3V6M  [C_0603]  85.36 61.3 90 top
CC1009  22U_0603_6.3V6M  [C_0603]  111.25 54.58 90 top
CC1010  22U_0603_6.3V6M  [C_0603]  110.08 59.43 270 top
CC1011  22U_0603_6.3V6M  [C_0603]  112.71 58.53 270 top
CC1015  22U_0603_6.3V6M  [C_0603]  112.47 54.58 90 top
CC1016  22U_0603_6.3V6M  [C_0603]  111.3 59.02 270 top
CC1052  180P_0402_50V8J  [C_0402]  108.97 53.24 270 top
CC1053  22U_0603_6.3V6M  [C_0603]  114.08 54.35 90 top
CC1054  22U_0603_6.3V6M  [C_0603]  113.9 58.53 270 top
CC1055  22U_0603_6.3V6M  [C_0603]  110 54.6 90 top
CC1057  22U_0603_6.3V6M  [C_0603]  86.63 61.3 90 top
CC1058  22U_0603_6.3V6M  [C_0603]  86.38 47.92 270 top
CC1059  22U_0603_6.3V6M  [C_0603]  81.55 61.3 90 top
CC1060  22U_0603_6.3V6M  [C_0603]  84.09 61.3 90 top
CC1061  22U_0603_6.3V6M  [C_0603]  87.9 61.3 90 top
CC1062  22U_0603_6.3V6M  [C_0603]  88.92 47.96 270 top
CC1063  22U_0603_6.3V6M  [C_0603]  80.28 61.3 90 top
CC1064  22U_0603_6.3V6M  [C_0603]  82.82 61.3 90 top
CC1065  22U_0603_6.3V6M  [C_0603]  85.11 47.92 270 top
CC1066  22U_0603_6.3V6M  [C_0603]  87.65 47.92 270 top
CC1067  180P_0402_50V8J  [C_0402]  115.62 53.03 270 top
CC1068  22U_0603_6.3V6M  [C_0603]  115.11 58.5 270 top
CC1078  0.22U_0402_10V6K  [C_0402]  121.37 59.12 90 top
CC1079  0.22U_0402_10V6K  [C_0402]  119.65 51.91 270 top
CC1080  10U_0603_6.3V6M  [C_0603]  89.68 37.04 270 top
CC1081  0.22U_0402_10V6K  [C_0402]  115.67 50.44 180 top
CC1082  0.22U_0402_10V6K  [C_0402]  116.53 50.44 0 top
CC1083  10U_0603_6.3V6M  [C_0603]  89.43 41.48 90 top
CC1084  0.22U_0402_10V6K  [C_0402]  120.16 59.12 90 top
CC1085  10U_0603_6.3V6M  [C_0603]  118.57 42.44 0 top
CC1086  0.22U_0402_10V6K  [C_0402]  117.75 48.65 90 top
CC1087  0.22U_0402_10V6K  [C_0402]  91.21 47.72 270 top
CC1088  0.22U_0402_10V6K  [C_0402]  92.22 61.28 90 top
CC1089  0.22U_0402_10V6K  [C_0402]  93.24 61.28 90 top
CC1090  0.22U_0402_10V6K  [C_0402]  95.27 61.28 90 top
CC1091  0.22U_0402_10V6K  [C_0402]  92.22 47.72 270 top
CC1092  0.22U_0402_10V6K  [C_0402]  93.24 47.72 270 top
CC1093  180P_0402_50V8J  [C_0402]  91.21 61.28 90 top
CC1095  22U_0603_6.3V6M  [C_0603]  118.32 52.98 0 top
CC1096  22U_0603_6.3V6M  [C_0603]  121.81 62.49 90 top
CC1097  22U_0603_6.3V6M  [C_0603]  118.26 56.15 0 top
CC1098  22U_0603_6.3V6M  [C_0603]  117.3 61.55 180 top
CC1100  22U_0603_6.3V6M  [C_0603]  117.05 37.36 0 top
CC1101  10U_0603_6.3V6M  [C_0603]  117.05 38.63 180 top
CC1102  0.22U_0402_10V6K  [C_0402]  116.49 48.72 180 top
CC1104  0.22U_0402_10V6K  [C_0402]  95.27 37.05 270 top
CC1105  0.22U_0402_10V6K  [C_0402]  93.24 37.05 270 top
CC1106  0.22U_0402_10V6K  [C_0402]  94.25 41.72 90 top
CC1107  0.22U_0402_10V6K  [C_0402]  95.27 41.72 90 top
CC1108  10U_0603_6.3V6M  [C_0603]  127.27 24.47 270 top
CC1109  10U_0603_6.3V6M  [C_0603]  126 24.47 270 top
CC1110  0.22U_0402_10V6K  [C_0402]  122.26 45.12 270 top
CC1111  0.22U_0402_10V6K  [C_0402]  89.17 61.28 90 top
CC1112  0.22U_0402_10V6K  [C_0402]  90.19 47.72 270 top
CC1113  0.22U_0402_10V6K  [C_0402]  95.27 47.72 270 top
CC1114  0.22U_0402_10V6K  [C_0402]  94.25 61.28 90 top
CC1115  180P_0402_50V8J  [C_0402]  94.25 47.72 270 top
CC1116  180P_0402_50V8J  [C_0402]  90.19 61.28 90 top
CC1117  0.22U_0402_10V6K  [C_0402]  138.18 67.25 270 top
CC1118  10U_0603_6.3V6M  [C_0603]  120.99 42.94 0 top
CC1119  0.22U_0402_10V6K  [C_0402]  118.64 48.65 90 top
CC1120  0.22U_0402_10V6K  [C_0402]  139.2 67.25 270 top
CC1121  0.22U_0402_10V6K  [C_0402]  140.25 67.23 270 top
CC1122  0.22U_0402_10V6K  [C_0402]  141.24 67.23 270 top
CC1123  0.22U_0402_10V6K  [C_0402]  142.62 67.87 270 top
CC1124  10U_0603_6.3V6M  [C_0603]  114.64 39.9 0 top
CC1125  0.22U_0402_10V6K  [C_0402]  144.71 67.85 270 top
CC1126  0.22U_0402_10V6K  [C_0402]  114.69 41.04 0 top
CC1127  0.22U_0402_10V6K  [C_0402]  143.67 67.9 270 top
CC1128  0.22U_0402_10V6K  [C_0402]  113.6 53.32 270 top
CC1129  0.22U_0402_10V6K  [C_0402]  134.72 36.28 180 top
CC1137  10U_0603_6.3V6M  [C_0603]  112.22 40.53 0 top
CC1139  0.22U_0402_10V6K  [C_0402]  117.44 54.44 180 top
CC1140  0.22U_0402_10V6K  [C_0402]  119.78 54.04 90 top
CC1141  0.22U_0402_10V6K  [C_0402]  117.44 52.47 180 top
CC1142  0.22U_0402_10V6K  [C_0402]  120.54 51.91 270 top
CC1143  0.22U_0402_10V6K  [C_0402]  110.45 51.26 270 top
CC1144  0.22U_0402_10V6K  [C_0402]  117.32 58.44 180 top
CC1145  0.22U_0402_10V6K  [C_0402]  117.32 56.41 180 top
CC1146  0.22U_0402_10V6K  [C_0402]  112.97 50.44 0 top
CC1147  10U_0603_6.3V6M  [C_0603]  90.7 41.48 90 top
CC1148  0.22U_0402_10V6K  [C_0402]  94.25 37.05 270 top
CC1150  0.22U_0402_10V6K  [C_0402]  92.22 37.05 270 top
CC1151  0.22U_0402_10V6K  [C_0402]  111.09 49.47 180 top
CD193  100P_0402_50V8J  [C_0402]  48.48 61.23 180 top
CD194  10U_0603_6.3V6M  [C_0603]  77.74 62.82 0 top
CD195  10U_0603_6.3V6M  [C_0603]  70.12 43.39 270 top
CD196  10U_0603_6.3V6M  [C_0603]  67.84 65.11 90 top
CD197  10U_0603_6.3V6M  [C_0603]  61.81 63.45 90 top
CD198  10U_0603_6.3V6M  [C_0603]  47.14 46.06 270 top
CD199  10U_0603_6.3V6M  [C_0603]  56.54 45.17 270 top
CD200  1U_0402_6.3V6K  [C_0402]  50.95 45.56 270 top
CD201  1U_0402_6.3V6K  [C_0402]  72.41 43.4 270 top
CD202  1U_0402_6.3V6K  [C_0402]  59.84 63.31 90 top
CD203  1U_0402_6.3V6K  [C_0402]  67.33 43.4 270 top
CD204  1U_0402_6.3V6K  [C_0402]  60.73 63.31 90 top
CD205  1U_0402_6.3V6K  [C_0402]  69.11 65.35 90 top
CD206  1U_0402_6.3V6K  [C_0402]  48.28 45.56 270 top
CD207  1U_0402_6.3V6K  [C_0402]  56.15 64.08 90 top
CD208  1U_0402_6.3V6K  [C_0402]  61.54 19.83 0 top
CD209  10U_0603_6.3V6M  [C_0603]  59.65 17.29 180 top
CD210  10U_0603_6.3V6M  [C_0603]  59.65 18.56 180 top
CD211  10P_0402_50V8J  [C_0402]  77.73 63.96 0 top
CD212  10P_0402_50V8J  [C_0402]  70.38 65.35 90 top
CD213  10P_0402_50V8J  [C_0402]  43.4 49.93 180 top
CD214  10P_0402_50V8J  [C_0402]  61.54 18.81 0 top
CD215  10P_0402_50V8J  [C_0402]  43.53 54.63 180 top
CD216  10P_0402_50V8J  [C_0402]  64.54 44.67 270 top
CD217  10P_0402_50V8J  [C_0402]  61.54 17.86 0 top
CD218  4.7U_0402_6.3V6K  [C_0402]  61.54 41.93 0 top
CD219  0.1U_0402_16V4Z  [C_0402]  61.54 43.96 0 top
CD220  0.1U_0402_16V4Z  [C_0402]  61.54 42.94 0 top
CD221  2.2U_0402_6.3V6M  [C_0402]  74.95 43.4 270 top
CD222  2.2U_0402_6.3V6M  [C_0402]  43.53 56.15 180 top
CD223  2.2U_0402_6.3V6M  [C_0402]  52.47 45.69 270 top
CD224  2.2U_0402_6.3V6M  [C_0402]  58.82 63.31 90 top
CD225  2.2U_0402_6.3V6M  [C_0402]  73.93 43.4 270 top
CD226  2.2U_0402_6.3V6M  [C_0402]  61.54 20.85 0 top
CD227  2.2U_0402_6.3V6M  [C_0402]  59.66 19.83 180 top
CD228  1000P_0402_50V7K  [C_0402]  61.54 40.91 0 top
CD229  330U_D2_2VY_R9M  [C_D3]  74.19 68.57 90 top
CD230  330U_D3_2.5VY_R6M  [C_D3]  81.81 47.16 270 top
CD231  1U_0402_6.3V6K  [C_0402]  68.9 20.59 0 top
CD232  10U_0603_6.3V6M  [C_0603]  68.92 23.01 0 top
CD233  10U_0603_6.3V6M  [C_0603]  68.92 21.74 0 top
CD234  1U_0402_6.3V6K  [C_0402]  71.52 22.29 90 top
CD237  1U_0402_6.3V6K  [C_0402]  68.9 19.58 0 top
CD239  10U_0603_6.3V6M  [C_0603]  54.63 45.23 270 top
CD240  10U_0603_6.3V6M  [C_0603]  43.64 51.07 180 top
CD241  10U_0603_6.3V6M  [C_0603]  42.76 58.69 180 top
CD242  10U_0603_6.3V6M  [C_0603]  42.76 45.99 180 top
CD243  10U_0603_6.3V6M  [C_0603]  52.73 63.58 90 top
CD244  10U_0603_6.3V6M  [C_0603]  42.76 57.42 180 top
CD245  1U_0402_6.3V6K  [C_0402]  43.4 48.15 180 top
CD246  1U_0402_6.3V6K  [C_0402]  50.06 45.56 270 top
CD247  1U_0402_6.3V6K  [C_0402]  53.49 45.69 270 top
CD248  1U_0402_6.3V6K  [C_0402]  54.25 63.31 90 top
CD249  1U_0402_6.3V6K  [C_0402]  50.82 63.57 90 top
CD250  1U_0402_6.3V6K  [C_0402]  57.17 64.08 90 top
CD251  1U_0402_6.3V6K  [C_0402]  43.53 53.1 180 top
CD252  1U_0402_6.3V6K  [C_0402]  49.17 45.56 270 top
CD253  1U_0402_6.3V6K  [C_0402]  45.44 22.31 180 top
CD254  10U_0603_6.3V6M  [C_0603]  46.82 19.96 180 top
CD255  10U_0603_6.3V6M  [C_0603]  46.82 21.23 180 top
CD256  1000P_0402_50V7K  [C_0402]  42.77 43.71 180 top
CD258  330U_D3_2.5VY_R6M  [C_D3]  41.95 66.5 180 top
CD259  1U_0402_6.3V6K  [C_0402]  53.61 19.84 270 top
CD260  10U_0603_6.3V6M  [C_0603]  54.69 19.83 270 top
CD261  10U_0603_6.3V6M  [C_0603]  55.96 19.83 270 top
CD262  1U_0402_6.3V6K  [C_0402]  52.47 22.67 90 top
CD265  1U_0402_6.3V6K  [C_0402]  52.73 19.84 270 top
CD266  4.7U_0402_6.3V6K  [C_0402]  42.77 42.69 180 top
CD267  0.1U_0402_16V4Z  [C_0402]  42.77 44.72 180 top
CD268  0.1U_0402_16V4Z  [C_0402]  44.52 44.72 0 top
CE3  0.1U_0402_16V7K  [C_0402]  166.59 36.85 180 top
CE4  0.1U_0402_16V7K  [C_0402]  181.3 33.61 0 top
CE10  1000P_0402_50V7K  [C_0402]  165.39 34.35 0 top
CE13  1000P_0402_50V7K  [C_0402]  182.28 28.21 180 top
CE14  0.1U_0402_16V7K  [C_0402]  179.85 23.34 270 top
CE17  0.1U_0402_16V7K  [C_0402]  178.8 38.98 270 top
CE20  0.1U_0402_16V7K  [C_0402]  160.85 92.73 0 top
CE21  0.1U_0402_16V7K  [C_0402]  165.88 25.21 90 top
CE23  0.1U_0402_16V7K  [C_0402]  178.58 20.54 270 bottom
CE24  22P_0402_50V8J  [C_0402]  186.25 32.28 0 bottom
CE25  0.1U_0402_16V7K  [C_0402]  184.88 33.8 180 bottom
CE33  0.1U_0402_16V7K  [C_0402]  186.25 31.26 0 bottom
CE39  0.1U_0402_16V7K  [C_0402]  164.87 20.54 270 bottom
CE40  100P_0402_50V8J  [C_0402]  173.12 41.75 270 bottom
CE41  1000P_0402_50V7K  [C_0402]  168.17 40.71 90 top
CE42  1000P_0402_50V7K  [C_0402]  169.18 41.62 270 top
CE43  100P_0402_50V8J  [C_0402]  167.91 19.63 90 bottom
CE47  0.1U_0402_16V7K  [C_0402]  166.14 40.71 90 bottom
CE56  1U_0603_10V6K  [C_0603]  123.21 11.77 90 bottom
CF4  22U_0805_10V6M  [C_0805]  182.99 49.29 180 bottom
CH1  0.01U_0402_16V7K  [C_0402]  94.06 73.88 270 top
CH2  0.01U_0402_16V7K  [C_0402]  94.3 75.71 0 top
CI1  0.1U_0402_10V7K  [C_0402]  21.66 85.72 0 top
CI2  0.1U_0402_10V7K  [C_0402]  21.66 84.7 0 top
CI3  0.1U_0402_10V7K  [C_0402]  20.52 88.35 0 top
CI4  0.1U_0402_10V7K  [C_0402]  20.52 87.33 0 top
CI5  0.1U_0402_10V7K  [C_0402]  20.58 82.72 0 top
CI6  0.1U_0402_10V7K  [C_0402]  20.58 81.7 0 top
CI7  0.1U_0402_10V7K  [C_0402]  21.53 80.03 0 top
CI8  0.1U_0402_10V7K  [C_0402]  21.53 79.01 0 top
CI9  .1U_0402_16V7K  [C_0402]  15.51 90.65 270 top
CI10  220P_0402_50V8J  [C_0402]  31.72 91.46 180 top
CI11  3.3P_0402_50V8C  [C_0402]  16.53 85.51 90 top
CI12  3.3P_0402_50V8C  [C_0402]  16.53 84.65 270 top
CI13  3.3P_0402_50V8C  [C_0402]  15.51 87.95 90 top
CI14  3.3P_0402_50V8C  [C_0402]  15.51 87.09 270 top
CI15  3.3P_0402_50V8C  [C_0402]  15.51 82.82 90 top
CI16  3.3P_0402_50V8C  [C_0402]  15.51 81.7 270 top
CI17  3.3P_0402_50V8C  [C_0402]  16.53 79.88 90 top
CI18  3.3P_0402_50V8C  [C_0402]  16.53 79.01 270 top
CL1  0.1U_0402_10V7K  [C_0402]  30.28 122.67 270 bottom
CL2  0.1U_0402_10V7K  [C_0402]  31.29 122.67 270 bottom
CL5  0.1U_0402_25V6  [C_0402]  35.33 117.16 90 top
CL6  0.1U_0402_25V6  [C_0402]  32.07 115.84 0 top
CL7  4.7U_0603_6.3V6K  [C_0603]  38.44 114.57 0 bottom
CL8  0.1U_0402_10V7K  [C_0402]  37.36 114.78 270 bottom
CL9  1U_0402_6.3V6K  [C_0402]  28.26 122.95 0 bottom
CL10  10P_0402_50V8J  [C_0402]  37.36 118.94 90 bottom
CL11  10P_0402_50V8J  [C_0402]  37.36 118.08 270 bottom
CL12  0.01U_0402_16V7K  [C_0402]  28.42 108.22 180 top
CL13  100P_1206_2KV8J  [C_1206]  22.69 118.38 180 bottom
CL14  0.1U_0402_25V6  [C_0402]  34.39 119.97 180 top
CLIP1  -  [EMIST_SQ-55G_1P]  92.24 91.8 0 bottom
CLIP2  -  [EMIST_SQ-55G_1P]  36.79 11.32 0 bottom
CLRP1  SHORT PADS  [SHORTPADS]  78.57 23.51 0 bottom
CS5  1000P_0402_50V7K  [C_0402]  193.52 17.04 180 top
CS6  0.1U_0402_25V6K  [C_0402]  194.63 17.04 0 top
CS7  10U_0805_10V6K  [C_0805]  194.75 15 0 top
CS8  0.01U_0402_16V7K  [C_0402]  183.9 46.44 0 bottom
CS9  0.01U_0402_16V7K  [C_0402]  183.9 45.55 0 bottom
CS10  1000P_0402_50V7K  [C_0402]  195.6 48.23 270 top
CS11  0.1U_0402_25V6K  [C_0402]  196.87 50.11 90 top
CS12  10U_0805_10V6K  [C_0805]  197.12 48.11 270 top
CS13  0.01U_0402_16V7K  [C_0402]  183.2 43.26 0 bottom
CS14  0.01U_0402_16V7K  [C_0402]  183.2 44.15 0 bottom
CS15  1U_0402_10V6K  [C_0402]  197.38 12.01 90 top
CS27  0.1U_0402_25V6K  [C_0402]  188.74 28.16 270 bottom
CS30  0.01U_0402_16V7K  [C_0402]  194.33 22.07 270 bottom
CS31  0.01U_0402_16V7K  [C_0402]  196.67 22.07 270 bottom
CS32  0.01U_0402_16V7K  [C_0402]  195.26 22.07 270 bottom
CS33  0.01U_0402_16V7K  [C_0402]  196.21 30.96 270 bottom
CS34  0.01U_0402_16V7K  [C_0402]  197.63 22.07 270 bottom
CS35  0.01U_0402_16V7K  [C_0402]  197.12 30.96 270 bottom
CS36  0.01U_0402_16V7K  [C_0402]  194.86 30.96 270 bottom
CS37  0.01U_0402_16V7K  [C_0402]  193.95 30.96 270 bottom
CS38  0.01U_0402_16V7K  [C_0402]  194.33 22.07 270 top
CS39  0.01U_0402_16V7K  [C_0402]  195.26 22.07 270 top
CS40  0.01U_0402_16V7K  [C_0402]  197.63 22.07 270 top
CS41  0.01U_0402_16V7K  [C_0402]  196.67 22.07 270 top
CS42  0.01U_0402_16V7K  [C_0402]  201.51 24.64 90 bottom
CU1  0.1U_0402_10V7K  [C_0402]  24.96 59.71 0 top
CU2  0.1U_0402_10V7K  [C_0402]  24.96 60.72 0 top
CU3  0.1U_0402_10V7K  [C_0402]  24.96 40.4 0 top
CU4  0.1U_0402_10V7K  [C_0402]  24.96 41.42 0 top
CU6  4.7U_0805_10V4Z  [C_0805]  22.03 70.12 0 top
CU7  0.1U_0402_16V7K  [C_0402]  22.68 68.6 0 top
CU8  0.1U_0402_16V7K  [C_0402]  24.66 67.28 270 top
CU9  0.1U_0402_16V7K  [C_0402]  24.66 64.33 90 top
CU10  15P_0402_50V8J  [C_0402]  27.44 56.51 90 top
CU11  47U_0805_6.3V4Z  [C_0805]  19.58 64.95 90 top
CU12  47U_0805_6.3V4Z  [C_0805]  17.8 64.95 90 top
CU13  10U_0603_10V6M  [C_0603]  19.07 63.2 270 top
CU14  0.1U_0402_16V7K  [C_0402]  17.8 63.21 270 top
CU15  15P_0402_50V8J  [C_0402]  25.98 37.1 0 top
CU16  47U_0805_6.3V4Z  [C_0805]  17.8 45.14 90 top
CU17  47U_0805_6.3V4Z  [C_0805]  19.58 45.14 90 top
CU18  10U_0603_10V6M  [C_0603]  19.58 43.64 270 top
CU19  0.1U_0402_16V7K  [C_0402]  18.31 43.15 270 top
CU20  4.7U_0805_10V4Z  [C_0805]  172.99 9.76 270 top
CU21  0.1U_0402_16V7K  [C_0402]  174.52 9.87 270 top
CU22  0.1U_0402_16V7K  [C_0402]  170.47 14.69 180 top
CU23  0.1U_0402_16V7K  [C_0402]  170.44 19.58 0 top
CV1  0.22U_0402_16V7K  [C_0402]  102.36 126.38 90 bottom
CV2  0.22U_0402_16V7K  [C_0402]  103.25 126.38 90 bottom
CV3  0.22U_0402_16V7K  [C_0402]  104.17 126.36 90 bottom
CV4  0.22U_0402_16V7K  [C_0402]  105.06 126.36 90 bottom
CV5  0.22U_0402_16V7K  [C_0402]  101.43 126.37 90 bottom
CV6  0.22U_0402_16V7K  [C_0402]  100.54 126.37 90 bottom
CV7  0.22U_0402_16V7K  [C_0402]  108.99 126.31 90 bottom
CV8  0.22U_0402_16V7K  [C_0402]  109.88 126.31 90 bottom
CV11  0.082U_0402_16V  [C_0402]  103.94 112.82 90 top
CV15  0.68U_0402_10V  [C_0402]  103.49 116.68 180 top
CV17  8.2P_0402_50V8D  [C_0402]  97.91 122.83 90 bottom
CV18  8.2P_0402_50V8D  [C_0402]  97.91 121.97 270 bottom
CV19  10U_0603_6.3V6M  [C_0603]  100.48 112.03 270 top
CV20  1U_0402_6.3V4Z  [C_0402]  106.91 111.65 270 top
CV21  0.1U_0402_10V6K  [C_0402]  106.01 111.47 270 top
CV26  1U_0402_6.3V4Z  [C_0402]  103.05 109.76 90 top
CV27  10U_0603_6.3V6M  [C_0603]  102.06 109.49 180 top
CV28  0.68U_0402_10V  [C_0402]  105.83 115.06 180 top
CV29  0.68U_0402_10V  [C_0402]  106.64 114.07 270 top
CV30  10U_0603_6.3V6M  [C_0603]  104.75 108.41 270 top
CV33  1U_0402_6.3V4Z  [C_0402]  106.73 109.13 270 top
CV34  0.1U_0402_10V6K  [C_0402]  105.83 109.13 270 top
CV35  0.1U_0402_10V6K  [C_0402]  104.75 109.85 90 top
CV38  10U_0603_6.3V6M  [C_0603]  96.29 125.81 180 bottom
CV39  0.1U_0402_10V6K  [C_0402]  103.27 119.52 45 top
CV40  2.2U_0402_6.3V6M  [C_0402]  116.52 109.76 270 top
CV41  2.2U_0402_6.3V6M  [C_0402]  134.54 127.92 90 top
CV42  2.2U_0402_6.3V6M  [C_0402]  117.23 116.77 180 top
CV43  10U_0603_6.3V6M  [C_0603]  138.49 127.99 90 top
CV44  10U_0603_6.3V6M  [C_0603]  139.76 127.99 90 top
CV45  10U_0603_6.3V6M  [C_0603]  141.03 127.99 90 top
CV46  1U_0402_6.3V4Z  [C_0402]  98.78 124.73 180 bottom
CV47  2.2U_0402_6.3V6M  [C_0402]  136.52 127.9 90 top
CV48  2.2U_0402_6.3V6M  [C_0402]  135.45 127.9 90 top
CV49  0.1U_0402_10V6K  [C_0402]  117.41 115.87 180 top
CV50  0.1U_0402_10V6K  [C_0402]  137.41 127.9 90 top
CV51  0.1U_0402_10V6K  [C_0402]  115.62 109.76 270 top
CV52  0.1U_0402_10V6K  [C_0402]  117.77 107.97 180 top
CV53  0.1U_0402_10V6K  [C_0402]  117.41 114.97 180 top
CV54  10U_0603_6.3V6M  [C_0603]  114.05 120.52 180 top
CV55  10U_0603_6.3V6M  [C_0603]  114.05 121.79 180 top
CV56  1U_0402_6.3V4Z  [C_0402]  115.53 118.44 135 top
CV57  1U_0402_6.3V4Z  [C_0402]  112.03 117.92 90 top
CV58  1U_0402_6.3V4Z  [C_0402]  113.81 117.92 90 top
CV59  1U_0402_6.3V4Z  [C_0402]  112.92 117.92 90 top
CV60  1U_0402_6.3V4Z  [C_0402]  115.79 119.46 135 top
CV61  10U_0603_6.3V6M  [C_0603]  100.1 115.27 90 top
CV62  1U_0402_6.3V4Z  [C_0402]  108.43 115.69 90 top
CV63  0.1U_0402_10V6K  [C_0402]  109.42 115.78 90 top
CV64  1U_0402_6.3V4Z  [C_0402]  99 115.06 90 bottom
CV65  1U_0402_6.3V4Z  [C_0402]  108.16 112.9 90 top
CV66  1U_0402_6.3V4Z  [C_0402]  109.06 113.62 90 top
CV67  10U_0603_6.3V6M  [C_0603]  91.27 127.15 90 top
CV68  10U_0603_6.3V6M  [C_0603]  90 127.14 90 top
CV69  10U_0603_6.3V6M  [C_0603]  88.73 127.14 90 top
CV70  10U_0603_6.3V6M  [C_0603]  87.46 127.15 90 top
CV71  1U_0402_6.3V4Z  [C_0402]  111.47 110.82 270 top
CV72  1U_0402_6.3V4Z  [C_0402]  114.36 110.84 90 top
CV73  1U_0402_6.3V4Z  [C_0402]  112.56 105.99 0 top
CV74  1U_0402_6.3V4Z  [C_0402]  112.01 108.85 270 top
CV75  1U_0402_6.3V4Z  [C_0402]  114.36 108.94 180 top
CV76  1U_0402_6.3V4Z  [C_0402]  109.59 108.87 90 top
CV77  1U_0402_6.3V4Z  [C_0402]  111.65 112.51 180 top
CV78  1U_0402_6.3V4Z  [C_0402]  114.32 114.65 180 top
CV79  1U_0402_6.3V4Z  [C_0402]  115.26 112.64 270 top
CV80  1U_0402_6.3V4Z  [C_0402]  107.46 121.25 270 top
CV81  10U_0603_6.3V6M  [C_0603]  117.5 103.75 270 top
CV82  1U_0402_6.3V4Z  [C_0402]  116.43 104.28 180 top
CV84  10U_0603_6.3V6M  [C_0603]  122.51 88.09 0 top
CV85  1U_0402_6.3V4Z  [C_0402]  120.04 101.95 270 top
CV86  0.1U_0402_10V6K  [C_0402]  120.91 101.94 0 top
CV87  1U_0402_6.3V4Z  [C_0402]  117.05 112.1 180 top
CV88  10U_0603_6.3V6M  [C_0603]  92.54 127.15 90 top
CV89  1U_0402_6.3V4Z  [C_0402]  116.52 114.07 0 top
CV90  1U_0402_6.3V4Z  [C_0402]  115.26 113.71 90 top
CV91  10U_0603_6.3V6M  [C_0603]  122.26 86.12 0 top
CV92  1U_0402_6.3V4Z  [C_0402]  120.91 102.82 0 top
CV93  0.1U_0402_10V6K  [C_0402]  121.13 104.31 90 top
CV94  1U_0402_6.3V4Z  [C_0402]  117.86 125.32 180 bottom
CV95  1U_0402_6.3V4Z  [C_0402]  119.64 126.21 180 bottom
CV96  120P_0402_50V8J  [C_0402]  125.05 88.46 90 top
CV97  68P_0402_50V8J  [C_0402]  119.54 102.82 180 top
CV98  0.1U_0402_16V4Z  [C_0402]  118.64 88.71 90 top
CV99  0.1U_0402_16V4Z  [C_0402]  117.24 100.53 90 top
CV100  1U_0402_6.3V4Z  [C_0402]  111.13 108.5 270 top
CV101  1U_0402_6.3V4Z  [C_0402]  114.2 109.82 180 top
CV102  1U_0402_6.3V4Z  [C_0402]  109.87 111.92 90 top
CV103  1U_0402_6.3V4Z  [C_0402]  112.56 111.56 0 top
CV104  1U_0402_6.3V4Z  [C_0402]  93.68 127.64 90 top
CV105  1U_0402_6.3V4Z  [C_0402]  114.33 113.79 180 top
CV106  1U_0402_6.3V4Z  [C_0402]  110.19 114.58 270 top
CV107  1U_0402_6.3V4Z  [C_0402]  89.62 125.06 270 top
CV108  1U_0402_6.3V4Z  [C_0402]  86.88 121.11 0 top
CV109  1U_0402_6.3V4Z  [C_0402]  86.88 122.07 0 top
CV110  1U_0402_6.3V4Z  [C_0402]  86.88 122.95 0 top
CV111  1U_0402_6.3V4Z  [C_0402]  110.62 115.83 90 top
CV112  1U_0402_6.3V4Z  [C_0402]  115.92 107.09 90 top
CV113  1U_0402_6.3V4Z  [C_0402]  94.7 127.64 90 top
CV114  1U_0402_6.3V4Z  [C_0402]  111.13 106.35 270 top
CV115  1U_0402_6.3V4Z  [C_0402]  112.56 112.64 90 top
CV116  1U_0402_6.3V4Z  [C_0402]  111.67 114.43 0 top
CV117  1U_0402_6.3V4Z  [C_0402]  110.59 110.8 270 top
CV118  1U_0402_6.3V4Z  [C_0402]  112.89 107.79 270 top
CV119  1U_0402_6.3V4Z  [C_0402]  88.67 125.06 270 top
CV120  1U_0402_6.3V4Z  [C_0402]  111.15 117.92 90 top
CV121  1U_0402_6.3V4Z  [C_0402]  114.7 117.82 270 top
CV122  10U_0603_6.3V6M  [C_0603]  111.78 123.02 0 top
CV123  10U_0603_6.3V6M  [C_0603]  96.67 114.76 180 bottom
CV124  0.1U_0402_10V6K  [C_0402]  116.87 105.27 180 top
CV125  0.1U_0402_10V6K  [C_0402]  112.43 105.07 0 top
CV126  0.1U_0402_10V6K  [C_0402]  91.4 125.06 270 top
CV127  0.1U_0402_10V6K  [C_0402]  90.51 125.06 270 top
CV153  0.1U_0402_10V6K  [C_0402]  140.44 94.63 90 bottom
CV155  0.1U_0402_10V6K  [C_0402]  153.14 119.23 0 top
CV157  0.1U_0402_10V6K  [C_0402]  153.21 126.15 0 bottom
CV158  0.1U_0402_10V6K  [C_0402]  153.21 127.16 0 bottom
CV160  0.1U_0402_10V6K  [C_0402]  153.2 125.2 0 bottom
CV161  0.1U_0402_10V6K  [C_0402]  153.2 124.25 0 bottom
CV162  0.1U_0402_10V6K  [C_0402]  147.7 95.55 270 bottom
CV164  0.1U_0402_10V6K  [C_0402]  148.78 95.55 270 bottom
CV165  0.1U_0402_10V6K  [C_0402]  153.4 109 0 bottom
CV166  0.1U_0402_10V6K  [C_0402]  153.4 97.7 0 top
CV169  1U_0402_6.3V4Z  [C_0402]  153.4 105.77 0 bottom
CV170  1U_0402_6.3V4Z  [C_0402]  153.4 104.69 0 bottom
CV173  1U_0402_6.3V4Z  [C_0402]  153.4 103.61 0 bottom
CV174  0.01U_0402_16V7K  [C_0402]  133.64 127.92 90 top
CV175  0.01U_0402_16V7K  [C_0402]  116.28 110.75 180 top
CV176  0.01U_0402_16V7K  [C_0402]  117.77 105.99 90 top
CV177  0.01U_0402_16V7K  [C_0402]  119.3 105.9 90 top
CV178  0.01U_0402_16V7K  [C_0402]  117.59 109.22 90 top
CV179  0.01U_0402_16V7K  [C_0402]  98.2 110.83 180 bottom
CV180  1U_0402_6.3V4Z  [C_0402]  115.26 116.05 180 top
CV181  1U_0402_6.3V4Z  [C_0402]  112.21 115.44 90 top
CV182  10U_0603_6.3V6M  [C_0603]  81.64 96.5 180 top
CV183  0.1U_0402_10V7K  [C_0402]  81.14 91.87 180 top
CV184  0.1U_0402_10V7K  [C_0402]  78.05 96.16 0 top
CV185  0.1U_0402_10V7K  [C_0402]  76.98 96.23 270 top
CV186  0.1U_0402_10V7K  [C_0402]  123.56 92.42 90 bottom
CV198  0.1U_0402_10V6K  [C_0402]  153.21 127.16 0 top
CV210  0.1U_0402_10V6K  [C_0402]  153.21 126.15 0 top
CV211  0.1U_0402_10V6K  [C_0402]  153.14 115.1 0 top
CV213  0.1U_0402_10V6K  [C_0402]  153.14 116.12 0 top
CV216  0.1U_0402_10V6K  [C_0402]  150.93 95.55 270 bottom
CV219  0.1U_0402_10V6K  [C_0402]  153.4 106.84 0 bottom
CV221  0.1U_0402_10V6K  [C_0402]  146.62 95.55 270 top
CV225  10U_0603_6.3V6M  [C_0603]  153.22 95.48 270 top
CV227  1U_0402_6.3V4Z  [C_0402]  153.4 107.92 0 top
CV230  0.1U_0402_10V6K  [C_0402]  152.34 127.98 90 top
CV233  0.1U_0402_10V6K  [C_0402]  150.44 127.98 90 top
CV235  0.1U_0402_10V6K  [C_0402]  147.54 127.96 90 top
CV238  10U_0603_6.3V6M  [C_0603]  142.27 127.99 90 top
CV242  1U_0402_6.3V4Z  [C_0402]  148.5 127.96 90 top
CV243  1U_0402_6.3V4Z  [C_0402]  149.46 127.98 90 top
CV247  1U_0402_6.3V4Z  [C_0402]  146.59 127.96 90 top
CV248  1U_0402_6.3V4Z  [C_0402]  151.4 127.98 90 top
CV304  0.22U_0402_16V7K  [C_0402]  119.91 68.65 90 bottom
CV305  0.22U_0402_16V7K  [C_0402]  119.59 73.73 90 bottom
CV306  0.22U_0402_16V7K  [C_0402]  125.05 69.35 90 bottom
CV307  0.22U_0402_16V7K  [C_0402]  122.58 67.44 90 bottom
CV308  0.22U_0402_16V7K  [C_0402]  120.48 73.73 90 bottom
CV309  0.22U_0402_16V7K  [C_0402]  121.69 67.44 90 bottom
CV312  0.22U_0402_16V7K  [C_0402]  125.94 69.35 90 bottom
CV313  0.22U_0402_16V7K  [C_0402]  120.8 68.65 90 bottom
CV333  1U_0402_6.3V4Z  [C_0402]  141.31 94.63 90 bottom
CV334  1U_0402_6.3V4Z  [C_0402]  153.2 123.23 0 bottom
CV335  1U_0402_6.3V4Z  [C_0402]  153.4 97.7 0 bottom
CV336  1U_0402_6.3V4Z  [C_0402]  153.4 96.62 0 bottom
CV341  1U_0402_6.3V4Z  [C_0402]  153.21 128.18 0 bottom
CV342  1U_0402_6.3V4Z  [C_0402]  153.12 118.51 0 bottom
CV343  1U_0402_6.3V4Z  [C_0402]  153.12 119.44 0 bottom
CV344  1U_0402_6.3V4Z  [C_0402]  153.11 120.4 0 bottom
CV390  1U_0402_6.3V6K  [C_0402]  153.4 100.75 0 top
CV391  1U_0402_6.3V6K  [C_0402]  144.46 95.55 270 bottom
CV394  1U_0402_6.3V6K  [C_0402]  153.14 123.29 0 top
CV395  1U_0402_6.3V6K  [C_0402]  144.69 127.96 90 bottom
CVT90  0.1U_0402_10V7K  [C_0402]  114.48 104.45 270 top
CW10  10U_0603_6.3V6M  [C_0603]  45.23 106.38 270 top
CW11  10U_0603_6.3V6M  [C_0603]  59.71 105.49 270 top
CW12  0.1U_0402_10V7K~D  [C_0402]  44.98 108.53 90 top
CW13  0.1U_0402_10V7K~D  [C_0402]  60.98 108.78 90 top
CW14  10P_0402_50V8J  [C_0402]  43.96 108.53 90 top
CW15  10P_0402_50V8J  [C_0402]  59.96 108.78 90 top
CW16  2.2U_0402_6.3V6M  [C_0402]  43.96 106.39 270 top
CW17  2.2U_0402_6.3V6M  [C_0402]  60.78 105.5 270 top
CX1  0.1U_0402_10V7K  [C_0402]  226.97 35.02 270 top
D4  -  [RB751V-40_SOD323-2]  173.25 35.63 270 top
DA1  AZ5125-02S.R7G_SOT23-3  [AZ5125-02SPR7G_SOT23-3]  8.66 8.37 180 bottom
DA2  AZ5125-02S.R7G_SOT23-3  [AZ5125-02SPR7G_SOT23-3]  12.72 8.37 180 bottom
DA3  -  [BAT54C-7-F_SOT23-3]  17.29 29.25 0 top
DA4  -  [L03ESDL5V0CC3-2_SOT23-3]  17.8 11.49 0 top
DA5  AZ5123-02S.R7G_SOT23-3  [AZ5123-02SPR7G_SOT23-3]  17.8 11.49 180 bottom
DC3  DB2J31400L SOD323-2  [RB751V-40TE17_SOD323-2]  138.42 49.42 270 top
DC3803  -  [BAS40C_SOT23-3]  35.1 6.88 270 bottom
DF1  -  [SDMK0340L-7-F_SOD323-2]  185.02 54.03 134.8 top
DH1  -  [DB2J31400L_SOD323-2]  83.87 74.57 180 top
DH2  -  [DB2J31400L_SOD323-2]  83.87 76.22 180 top
DU1  -  [AZC199-02SPR7G_SOT23-3]  164.89 15.51 270 bottom
DX1  -  [RB751V-40_SOD323-2]  221.25 37.05 90 top
DX2  -  [PESD5V0U2BT_SOT23-3]  221.53 31.26 270 bottom
EC2901  1000P_0402_50V7K  [C_0402]  160.85 93.74 0 top
EC2902  .1U_0402_16V7K  [C_0402]  156.43 108.22 180 top
ED2901  -  [AZ5725-01F_DFN2]  160.89 94.76 0 top
EU2601  -  [L05ESDL5V0NA-4_SLP2510P8-10-9]  18.48 58.14 270 top
EU2602  -  [AZC199-02SPR7G_SOT23-3]  18.03 55.14 270 top
EU2603  -  [L05ESDL5V0NA-4_SLP2510P8-10-9]  18.36 38.45 270 top
EU2604  -  [AZC199-02SPR7G_SOT23-3]  18.03 35.45 270 top
EU3501  -  [TVWDF1004AD0_DFN9]  31.45 111.51 270 bottom
F1  SMD1812P150TF/24 1.5A UL/CSA/TUV  [F_SMD1812P110TF-24]  220.93 51.58 0 top
F2  1.1A_24V_SMD1812P110TF-24  [F_SMD1812P110TF-24]  228.95 29.74 180 top
F3  0.5A_13.2V_MF-NSMF050-2  [F_MF-NSMF050-2]  118.34 11.7 0 bottom
FD1  FIDUCAL  [FIDUCIAL_C40M80]  16.28 121.68 180 bottom
FD2  FIDUCIAL  [FIDUCIAL_C40M80]  227.86 23.39 180 bottom
FD3  FIDUCAL  [FIDUCIAL_C40M80]  16.28 121.68 0 top
FD4  FIDUCIAL  [FIDUCIAL_C40M80]  227.86 11.96 0 top
FI1  1.5A_6V_1206L150PR~D  [F_1206L150PR]  16.91 89.98 0 top
H1  HOLEA  [H_3P0-G]  18.4 4.3 0 top
H2  HOLEA  [H_3P0-G]  8.7 122.3 0 top
H3  HOLEA  [H_3P0-G]  141.9 6.3 0 top
H4  HOLEA  [H_3P0-G]  206.6 47.9 0 top
H5  HOLEA  [H_3P0-G]  141.9 61.2 0 top
H6  HOLEA  [H_5P6N]  18.3 94.3 0 top
